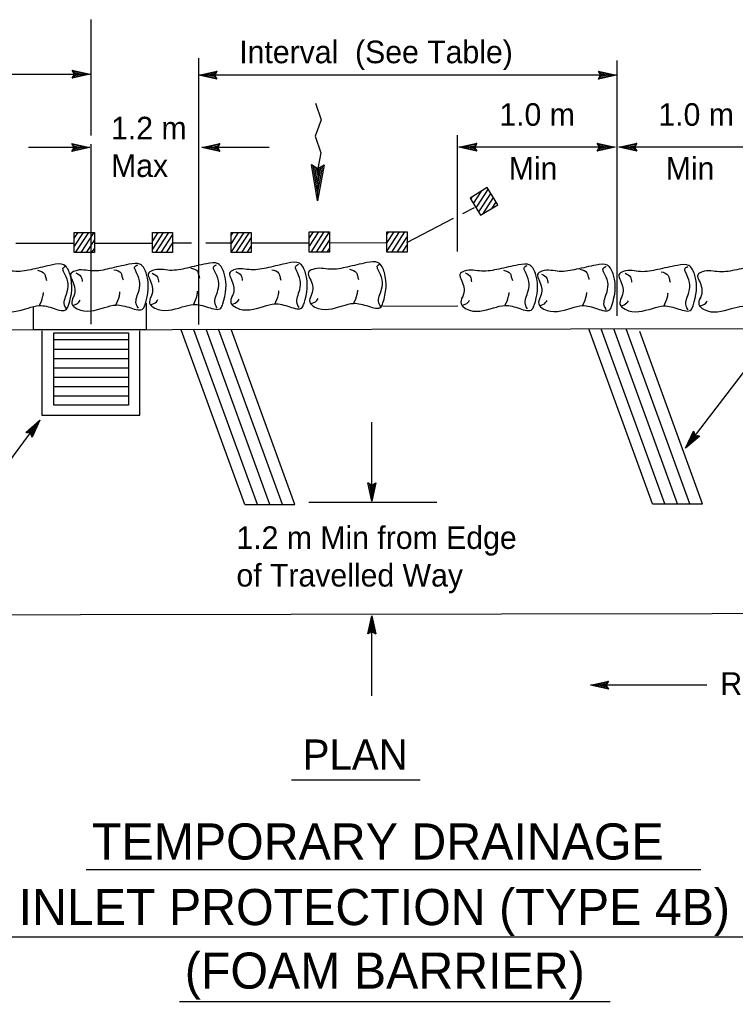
# Model space of a CAD drawing. Extents: x 6707406 to 6714471, y 1868570 to 1872341.
# Drawn here: x 6709693.1 to 6709921.3, y 1871409.2 to 1871722.3 of the extents above; entities that cross this region are included whole.
import ezdxf

# ---------------------------------------------------------------- set-up
doc = ezdxf.new("R2010")
doc.units = 0
for name, color, linetype in [('1 Control', 7, 'Continuous'), ('57 Undefined', 7, 'Continuous'), ('60 Nongeo Data', 7, 'Continuous'), ('63 Undefined', 7, 'Continuous')]:
    doc.layers.add(name, color=color, linetype=linetype)

msp = doc.modelspace()

# ---------------------------------------------------------------- linework, layer by layer
at = {"layer": '1 Control'}
for p, q in [((6709842.49, 1871668.29), (6709838.6, 1871662.29)), ((6709837.44, 1871665.8), (6709836.94, 1871665.03)), ((6709840.28, 1871667.52), (6709837.77, 1871663.66)), ((6709843.32, 1871666.92), (6709839.43, 1871660.93)), ((6709844.15, 1871665.55), (6709840.71, 1871660.25)), ((6709844.98, 1871664.19), (6709843.54, 1871661.97)), ((6709713.36, 1871654.41), (6709710.54, 1871650.07)), ((6709711.64, 1871654.41), (6709710.54, 1871652.71)), ((6709715.08, 1871654.41), (6709710.89, 1871647.97)), ((6709716.79, 1871654.41), (6709712.61, 1871647.97)), ((6709716.98, 1871652.05), (6709714.33, 1871647.97)), ((6709738.92, 1871654.41), (6709735.48, 1871649.11)), ((6709737.2, 1871654.41), (6709735.48, 1871651.75)), ((6709735.49, 1871654.41), (6709735.48, 1871654.39)), ((6709740.64, 1871654.41), (6709736.46, 1871647.97)), ((6709741.91, 1871653.73), (6709738.17, 1871647.97)), ((6709764.57, 1871654.41), (6709760.53, 1871648.19)), ((6709762.85, 1871654.41), (6709760.53, 1871650.84)), ((6709761.13, 1871654.41), (6709760.53, 1871653.48)), ((6709766.28, 1871654.41), (6709762.1, 1871647.97)), ((6709766.97, 1871652.82), (6709763.82, 1871647.97)), ((6709788.42, 1871654.6), (6709785.47, 1871650.05)), ((6709786.7, 1871654.6), (6709785.47, 1871652.7)), ((6709790.14, 1871654.6), (6709785.96, 1871648.16)), ((6709791.85, 1871654.6), (6709787.67, 1871648.16)), ((6709791.9, 1871652.03), (6709789.39, 1871648.16)), ((6709814.16, 1871654.6), (6709810.22, 1871648.53)), ((6709812.44, 1871654.6), (6709810.22, 1871651.17)), ((6709810.73, 1871654.6), (6709810.22, 1871653.82)), ((6709815.88, 1871654.6), (6709811.7, 1871648.16)), ((6709816.65, 1871653.15), (6709813.41, 1871648.16)), ((6709716.98, 1871649.4), (6709716.05, 1871647.97)), ((6709741.91, 1871651.08), (6709739.89, 1871647.97)), ((6709766.97, 1871650.17), (6709765.54, 1871647.97)), ((6709791.9, 1871649.39), (6709791.11, 1871648.16)), ((6709816.65, 1871650.51), (6709815.13, 1871648.16)), ((6709741.91, 1871648.44), (6709741.61, 1871647.97))]:
    msp.add_line(p, q, dxfattribs=at)
for points in [[(6709842.23, 1871668.71), (6709836.73, 1871665.37), (6709840.07, 1871659.87), (6709845.57, 1871663.2)], [(6709710.54, 1871654.41), (6709716.98, 1871654.41), (6709716.98, 1871647.97), (6709710.54, 1871647.97)], [(6709735.48, 1871654.41), (6709741.91, 1871654.41), (6709741.91, 1871647.97), (6709735.48, 1871647.97)], [(6709760.53, 1871654.41), (6709766.97, 1871654.41), (6709766.97, 1871647.97), (6709760.53, 1871647.97)], [(6709785.47, 1871654.6), (6709791.9, 1871654.6), (6709791.9, 1871648.16), (6709785.47, 1871648.16)], [(6709810.22, 1871654.6), (6709816.65, 1871654.6), (6709816.65, 1871648.16), (6709810.22, 1871648.16)]]:
    msp.add_lwpolyline(points, close=True, dxfattribs=at)
at = {"layer": '57 Undefined'}
for p, q in [((6709715.85, 1871722.28), (6709715.85, 1871685.32)), ((6709750.26, 1871625.05), (6709750.26, 1871709.96)), ((6709883.68, 1871627.81), (6709883.68, 1871709.2)), ((6709588.34, 1871704.86), (6709715.63, 1871704.86)), ((6709883.41, 1871704.6), (6709750.29, 1871704.6)), ((6709832.72, 1871648.29), (6709832.72, 1871685.42)), ((6709715.55, 1871681.47), (6709696, 1871681.47)), ((6709715.85, 1871682.57), (6709715.85, 1871625.12)), ((6709772.68, 1871681.47), (6709751.21, 1871681.47)), ((6709883.02, 1871681.58), (6709833.18, 1871681.58)), ((6709934.78, 1871681.58), (6709884.17, 1871681.58)), ((6709905.48, 1871585.64), (6709978.12, 1871680.81)), ((6709668.01, 1871551.82), (6709699.53, 1871594.51)), ((6709805.46, 1871568.74), (6709805.46, 1871593.84)), ((6709826.16, 1871568.32), (6709785.33, 1871568.32)), ((6709805.46, 1871506.6), (6709805.46, 1871532.11)), ((6709912.24, 1871510.02), (6709875.09, 1871510.02)), ((6709779.84, 1871479.86), (6709820.79, 1871479.86)), ((6709714.3, 1871451.17), (6709910.3, 1871451.17)), ((6709677.29, 1871429.73), (6709944.39, 1871429.73)), ((6709744.07, 1871409.15), (6709881.4, 1871409.15))]:
    msp.add_line(p, q, dxfattribs=at)
at = {"layer": '60 Nongeo Data'}
for p, q in [((6709709.87, 1871706.15), (6709709.87, 1871706.15)), ((6709756.05, 1871705.87), (6709756.05, 1871705.87)), ((6709877.65, 1871705.88), (6709877.65, 1871705.88)), ((6709709.87, 1871703.59), (6709709.87, 1871703.59)), ((6709715.63, 1871704.86), (6709715.63, 1871704.86)), ((6709750.29, 1871704.6), (6709750.29, 1871704.6)), ((6709756.05, 1871703.31), (6709756.05, 1871703.31)), ((6709877.65, 1871703.32), (6709877.65, 1871703.32)), ((6709883.41, 1871704.6), (6709883.41, 1871704.6)), ((6709709.8, 1871682.75), (6709709.8, 1871682.75)), ((6709715.55, 1871681.47), (6709715.55, 1871681.47)), ((6709751.21, 1871681.47), (6709751.21, 1871681.47)), ((6709756.97, 1871682.74), (6709756.97, 1871682.74)), ((6709833.18, 1871681.58), (6709833.18, 1871681.58)), ((6709838.94, 1871682.86), (6709838.94, 1871682.86)), ((6709838.94, 1871680.29), (6709838.94, 1871680.29)), ((6709877.26, 1871682.87), (6709877.26, 1871682.87)), ((6709877.26, 1871680.3), (6709877.26, 1871680.3)), ((6709883.02, 1871681.58), (6709883.02, 1871681.58)), ((6709884.17, 1871681.58), (6709884.17, 1871681.58)), ((6709889.93, 1871682.86), (6709889.93, 1871682.86)), ((6709889.93, 1871680.29), (6709889.93, 1871680.29)), ((6709709.8, 1871680.19), (6709709.8, 1871680.19)), ((6709756.97, 1871680.18), (6709756.97, 1871680.18)), ((6709764.96, 1871567.62), (6709744.67, 1871623.38)), ((6709768.94, 1871567.63), (6709748.65, 1871623.37)), ((6709772.92, 1871567.63), (6709752.57, 1871623.56)), ((6709776.9, 1871567.64), (6709756.55, 1871623.56)), ((6709780.89, 1871567.65), (6709760.64, 1871623.27)), ((6709894.89, 1871567.85), (6709874.57, 1871623.68)), ((6709898.88, 1871567.83), (6709878.55, 1871623.69)), ((6709902.87, 1871567.83), (6709882.54, 1871623.69)), ((6709906.85, 1871567.83), (6709886.52, 1871623.7)), ((6709910.82, 1871567.87), (6709890.82, 1871622.81)), ((6709704.01, 1871620.22), (6709727.8, 1871620.22)), ((6709704.01, 1871617.22), (6709727.8, 1871617.22)), ((6709704.01, 1871614.23), (6709727.8, 1871614.23)), ((6709704.01, 1871611.23), (6709727.8, 1871611.23)), ((6709704.01, 1871608.24), (6709727.8, 1871608.24)), ((6709704.01, 1871605.24), (6709727.8, 1871605.24)), ((6709704.01, 1871602.25), (6709727.8, 1871602.25)), ((6709699.53, 1871594.51), (6709699.53, 1871594.51)), ((6709695.07, 1871590.64), (6709695.07, 1871590.64)), ((6709907.96, 1871590.99), (6709907.96, 1871590.99)), ((6709909.99, 1871589.43), (6709909.99, 1871589.43)), ((6709697.13, 1871589.12), (6709697.13, 1871589.12)), ((6709905.48, 1871585.64), (6709905.48, 1871585.64)), ((6709804.19, 1871574.5), (6709804.19, 1871574.5)), ((6709806.75, 1871574.5), (6709806.75, 1871574.5)), ((6709805.46, 1871568.74), (6709805.46, 1871568.74)), ((6709805.46, 1871532.11), (6709805.46, 1871532.11)), ((6709804.18, 1871526.35), (6709804.18, 1871526.35)), ((6709806.74, 1871526.35), (6709806.74, 1871526.35)), ((6709880.85, 1871511.29), (6709880.85, 1871511.29)), ((6709875.09, 1871510.02), (6709875.09, 1871510.02)), ((6709880.85, 1871508.73), (6709880.85, 1871508.73))]:
    msp.add_line(p, q, dxfattribs=at)
for points in [[(6709709.87, 1871706.15), (6709715.63, 1871704.86), (6709709.87, 1871703.59), (6709710.08, 1871703.93), (6709714.3, 1871704.86), (6709710.08, 1871705.81), (6709710.28, 1871705.47), (6709712.98, 1871704.87), (6709710.28, 1871704.27), (6709710.49, 1871704.61), (6709711.65, 1871704.87), (6709710.48, 1871705.13), (6709710.64, 1871704.86), (6709709.87, 1871703.59), (6709710.64, 1871704.86)], [(6709756.05, 1871703.31), (6709750.29, 1871704.6), (6709756.05, 1871705.87), (6709755.85, 1871705.53), (6709751.63, 1871704.6), (6709755.85, 1871703.65), (6709755.64, 1871703.99), (6709752.94, 1871704.59), (6709755.64, 1871705.19), (6709755.44, 1871704.85), (6709754.27, 1871704.59), (6709755.44, 1871704.33), (6709755.28, 1871704.6), (6709756.05, 1871705.87), (6709755.28, 1871704.6)], [(6709877.65, 1871705.88), (6709883.41, 1871704.6), (6709877.65, 1871703.32), (6709877.85, 1871703.66), (6709882.07, 1871704.59), (6709877.85, 1871705.54), (6709878.05, 1871705.2), (6709880.75, 1871704.6), (6709878.05, 1871704), (6709878.26, 1871704.34), (6709879.43, 1871704.6), (6709878.26, 1871704.86), (6709878.41, 1871704.6), (6709877.65, 1871703.32), (6709878.41, 1871704.6)], [(6709709.8, 1871682.75), (6709715.55, 1871681.47), (6709709.79, 1871680.19), (6709710, 1871680.53), (6709714.22, 1871681.46), (6709710, 1871682.41), (6709710.2, 1871682.07), (6709712.9, 1871681.47), (6709710.2, 1871680.87), (6709710.41, 1871681.21), (6709711.58, 1871681.47), (6709710.41, 1871681.73), (6709710.56, 1871681.47), (6709709.79, 1871680.19), (6709710.56, 1871681.47)], [(6709756.97, 1871680.18), (6709751.21, 1871681.47), (6709756.97, 1871682.74), (6709756.77, 1871682.4), (6709752.55, 1871681.47), (6709756.77, 1871680.52), (6709756.56, 1871680.86), (6709753.86, 1871681.47), (6709756.56, 1871682.06), (6709756.36, 1871681.72), (6709755.19, 1871681.46), (6709756.36, 1871681.2), (6709756.2, 1871681.47), (6709756.97, 1871682.74), (6709756.2, 1871681.47)], [(6709838.94, 1871680.29), (6709833.18, 1871681.58), (6709838.94, 1871682.86), (6709838.74, 1871682.52), (6709834.52, 1871681.58), (6709838.74, 1871680.64), (6709838.53, 1871680.98), (6709835.83, 1871681.58), (6709838.53, 1871682.18), (6709838.33, 1871681.84), (6709837.16, 1871681.58), (6709838.33, 1871681.32), (6709838.17, 1871681.58), (6709838.94, 1871682.86), (6709838.17, 1871681.58)], [(6709877.26, 1871682.87), (6709883.02, 1871681.58), (6709877.26, 1871680.3), (6709877.47, 1871680.64), (6709881.69, 1871681.58), (6709877.47, 1871682.53), (6709877.67, 1871682.19), (6709880.37, 1871681.58), (6709877.67, 1871680.99), (6709877.88, 1871681.33), (6709879.04, 1871681.58), (6709877.87, 1871681.85), (6709878.03, 1871681.58), (6709877.26, 1871680.3), (6709878.03, 1871681.58)], [(6709889.93, 1871680.29), (6709884.17, 1871681.58), (6709889.93, 1871682.86), (6709889.73, 1871682.52), (6709885.51, 1871681.58), (6709889.73, 1871680.64), (6709889.53, 1871680.98), (6709886.82, 1871681.58), (6709889.52, 1871682.18), (6709889.32, 1871681.84), (6709888.15, 1871681.58), (6709889.32, 1871681.32), (6709889.16, 1871681.58), (6709889.93, 1871682.86), (6709889.16, 1871681.58)], [(6709704.01, 1871622.39), (6709727.8, 1871622.39), (6709727.8, 1871599.26), (6709704.01, 1871599.26)], [(6709695.07, 1871590.64), (6709699.53, 1871594.51), (6709697.13, 1871589.12), (6709696.98, 1871589.49), (6709698.74, 1871593.44), (6709695.47, 1871590.6), (6709695.86, 1871590.57), (6709697.95, 1871592.38), (6709696.83, 1871589.85), (6709696.68, 1871590.22), (6709697.16, 1871591.31), (6709696.26, 1871590.53), (6709696.56, 1871590.5), (6709697.13, 1871589.12), (6709696.56, 1871590.5)], [(6709909.99, 1871589.43), (6709905.48, 1871585.64), (6709907.96, 1871590.99), (6709908.1, 1871590.62), (6709906.28, 1871586.7), (6709909.6, 1871589.48), (6709909.2, 1871589.52), (6709907.09, 1871587.74), (6709908.25, 1871590.25), (6709908.39, 1871589.88), (6709907.89, 1871588.8), (6709908.81, 1871589.57), (6709908.5, 1871589.6), (6709907.96, 1871590.99), (6709908.5, 1871589.6)], [(6709806.75, 1871574.5), (6709805.46, 1871568.74), (6709804.19, 1871574.5), (6709804.53, 1871574.29), (6709805.46, 1871570.07), (6709806.41, 1871574.29), (6709806.07, 1871574.09), (6709805.47, 1871571.39), (6709804.87, 1871574.09), (6709805.21, 1871573.88), (6709805.47, 1871572.72), (6709805.73, 1871573.89), (6709805.46, 1871573.73), (6709804.19, 1871574.5), (6709805.46, 1871573.73)], [(6709804.18, 1871526.35), (6709805.46, 1871532.11), (6709806.74, 1871526.35), (6709806.4, 1871526.55), (6709805.47, 1871530.77), (6709804.52, 1871526.55), (6709804.86, 1871526.75), (6709805.46, 1871529.46), (6709806.06, 1871526.76), (6709805.72, 1871526.96), (6709805.46, 1871528.13), (6709805.2, 1871526.96), (6709805.46, 1871527.12), (6709806.74, 1871526.35), (6709805.46, 1871527.12)], [(6709880.85, 1871508.73), (6709875.09, 1871510.02), (6709880.85, 1871511.29), (6709880.65, 1871510.95), (6709876.43, 1871510.02), (6709880.65, 1871509.07), (6709880.44, 1871509.41), (6709877.74, 1871510.01), (6709880.44, 1871510.61), (6709880.24, 1871510.27), (6709879.07, 1871510.01), (6709880.24, 1871509.75), (6709880.08, 1871510.02), (6709880.85, 1871511.29), (6709880.08, 1871510.02)]]:
    msp.add_lwpolyline(points, close=True, dxfattribs=at)
for points in [[(6709834.39, 1871660.45), (6709838.15, 1871662.4)], [(6709816.54, 1871651.16), (6709831.45, 1871658.92)], [(6709691.87, 1871650.96), (6709710.37, 1871650.99)], [(6709716.99, 1871651), (6709735.4, 1871651.03)], [(6709742.03, 1871651.04), (6709747.94, 1871651.05)], [(6709752.53, 1871651.06), (6709760.39, 1871651.07)], [(6709767.14, 1871651.08), (6709785.43, 1871651.11)], [(6709791.92, 1871651.12), (6709809.92, 1871651.15)], [(6709697.4, 1871630.53), (6709697.4, 1871623.44), (6709733.57, 1871623.44), (6709733.57, 1871631.87)], [(6709808.89, 1871630.92), (6709832.88, 1871630.96)], [(6709678.2, 1871623.36), (6709932.4, 1871623.77)], [(6709700.23, 1871622.97), (6709700.23, 1871596.11), (6709731.47, 1871596.11), (6709731.47, 1871622.97)], [(6709764.96, 1871567.62), (6709780.89, 1871567.65)], [(6709894.89, 1871567.85), (6709910.82, 1871567.87)], [(6709578.14, 1871532.3), (6710048.25, 1871533.08)]]:
    msp.add_lwpolyline(points, dxfattribs=at)
for points in [[(6709685.81, 1871633.55), (6709685.41, 1871631.49), (6709687.07, 1871629.88), (6709695.81, 1871630.27), (6709699.39, 1871631.08), (6709704.17, 1871630.12), (6709708.12, 1871629.94), (6709708.74, 1871631.23), (6709709.2, 1871640.9), (6709707.25, 1871644.03), (6709703.6, 1871644.06), (6709697.36, 1871642.67), (6709691.88, 1871641.95), (6709686.33, 1871641.92), (6709684.96, 1871640.86), (6709685.47, 1871639.03), (6709686.2, 1871634.53), (6709685.73, 1871633.32)], [(6709708.12, 1871629.86), (6709707.45, 1871631.24), (6709708.32, 1871635.57), (6709708.49, 1871638.62), (6709707.15, 1871641.98), (6709706.93, 1871642.89), (6709707.93, 1871643.72)], [(6709710.2, 1871633.73), (6709709.8, 1871631.68), (6709711.46, 1871630.07), (6709720.2, 1871630.45), (6709723.78, 1871631.26), (6709728.56, 1871630.31), (6709732.51, 1871630.12), (6709733.13, 1871631.41), (6709733.59, 1871641.08), (6709731.64, 1871644.22), (6709727.99, 1871644.25), (6709721.75, 1871642.85), (6709716.27, 1871642.13), (6709710.72, 1871642.1), (6709709.35, 1871641.05), (6709709.86, 1871639.21), (6709710.59, 1871634.72), (6709710.12, 1871633.5)], [(6709730.99, 1871630.25), (6709730.31, 1871631.63), (6709731.19, 1871635.96), (6709731.36, 1871639), (6709730.02, 1871642.36), (6709729.8, 1871643.28), (6709730.79, 1871644.11)], [(6709734.97, 1871633.91), (6709734.57, 1871631.86), (6709736.23, 1871630.25), (6709744.97, 1871630.63), (6709748.55, 1871631.44), (6709753.33, 1871630.49), (6709757.28, 1871630.3), (6709757.9, 1871631.59), (6709758.36, 1871641.26), (6709756.41, 1871644.4), (6709752.76, 1871644.43), (6709746.52, 1871643.03), (6709741.04, 1871642.31), (6709735.49, 1871642.28), (6709734.12, 1871641.23), (6709734.63, 1871639.4), (6709735.36, 1871634.9), (6709734.89, 1871633.68)], [(6709747.59, 1871643.1), (6709749.86, 1871641.94), (6709750.15, 1871641.02), (6709750.52, 1871639.8)], [(6709756.14, 1871630.24), (6709755.46, 1871631.61), (6709756.34, 1871635.95), (6709756.51, 1871638.99), (6709755.17, 1871642.35), (6709754.95, 1871643.27), (6709755.94, 1871644.1)], [(6709760.88, 1871634.08), (6709760.49, 1871632.03), (6709762.15, 1871630.42), (6709770.89, 1871630.8), (6709774.47, 1871631.61), (6709779.25, 1871630.66), (6709783.2, 1871630.48), (6709783.81, 1871631.77), (6709784.27, 1871641.43), (6709782.32, 1871644.57), (6709778.67, 1871644.6), (6709772.43, 1871643.2), (6709766.95, 1871642.48), (6709761.41, 1871642.45), (6709760.03, 1871641.4), (6709760.55, 1871639.57), (6709761.27, 1871635.07), (6709760.81, 1871633.85)], [(6709782.24, 1871630.41), (6709781.57, 1871631.78), (6709782.44, 1871636.12), (6709782.62, 1871639.16), (6709781.28, 1871642.52), (6709781.06, 1871643.44), (6709782.05, 1871644.27)], [(6709786.04, 1871634.26), (6709785.64, 1871632.21), (6709787.3, 1871630.6), (6709796.04, 1871630.98), (6709799.62, 1871631.79), (6709804.4, 1871630.84), (6709808.35, 1871630.65), (6709808.96, 1871631.94), (6709809.42, 1871641.61), (6709807.47, 1871644.75), (6709803.83, 1871644.77), (6709797.58, 1871643.38), (6709792.11, 1871642.66), (6709786.56, 1871642.63), (6709785.18, 1871641.58), (6709785.7, 1871639.74), (6709786.42, 1871635.25), (6709785.96, 1871634.03)], [(6709798.26, 1871642.69), (6709800.53, 1871641.53), (6709800.83, 1871640.61), (6709801.2, 1871639.39)], [(6709808.35, 1871630.58), (6709807.67, 1871631.95), (6709808.54, 1871636.29), (6709808.72, 1871639.33), (6709807.38, 1871642.69), (6709807.16, 1871643.61), (6709808.15, 1871644.44)], [(6709834.27, 1871633.71), (6709833.86, 1871631.67), (6709835.5, 1871630.04), (6709844.24, 1871630.34), (6709847.83, 1871631.11), (6709852.6, 1871630.11), (6709856.55, 1871629.89), (6709857.18, 1871631.17), (6709857.73, 1871640.83), (6709855.81, 1871643.99), (6709852.17, 1871644.05), (6709845.91, 1871642.72), (6709840.43, 1871642.06), (6709834.88, 1871642.08), (6709833.49, 1871641.04), (6709833.99, 1871639.2), (6709834.67, 1871634.7), (6709834.19, 1871633.49)], [(6709855.03, 1871630.03), (6709854.37, 1871631.41), (6709855.28, 1871635.74), (6709855.49, 1871638.78), (6709854.18, 1871642.15), (6709853.97, 1871643.07), (6709854.97, 1871643.89)], [(6709859.04, 1871633.65), (6709858.63, 1871631.6), (6709860.27, 1871629.97), (6709869.02, 1871630.27), (6709872.6, 1871631.05), (6709877.37, 1871630.05), (6709881.32, 1871629.82), (6709881.95, 1871631.11), (6709882.5, 1871640.77), (6709880.58, 1871643.93), (6709876.94, 1871643.99), (6709870.68, 1871642.66), (6709865.2, 1871641.99), (6709859.65, 1871642.02), (6709858.26, 1871640.98), (6709858.76, 1871639.14), (6709859.44, 1871634.63), (6709858.96, 1871633.42)], [(6709871.75, 1871642.71), (6709874.01, 1871641.53), (6709874.3, 1871640.61), (6709874.65, 1871639.39)], [(6709880.18, 1871629.77), (6709879.52, 1871631.15), (6709880.43, 1871635.48), (6709880.64, 1871638.52), (6709879.33, 1871641.89), (6709879.12, 1871642.81), (6709880.12, 1871643.63)], [(6709884.96, 1871633.57), (6709884.54, 1871631.52), (6709886.19, 1871629.89), (6709894.93, 1871630.19), (6709898.52, 1871630.96), (6709903.29, 1871629.96), (6709907.23, 1871629.74), (6709907.86, 1871631.02), (6709908.42, 1871640.69), (6709906.5, 1871643.84), (6709902.85, 1871643.91), (6709896.6, 1871642.57), (6709891.11, 1871641.91), (6709885.57, 1871641.93), (6709884.18, 1871640.89), (6709884.68, 1871639.05), (6709885.36, 1871634.55), (6709884.88, 1871633.34)], [(6709906.28, 1871629.68), (6709905.62, 1871631.06), (6709906.53, 1871635.39), (6709906.74, 1871638.43), (6709905.43, 1871641.8), (6709905.22, 1871642.72), (6709906.22, 1871643.54)], [(6709910.11, 1871633.5), (6709909.69, 1871631.45), (6709911.34, 1871629.82), (6709920.08, 1871630.12), (6709923.67, 1871630.89), (6709928.44, 1871629.89), (6709932.39, 1871629.67), (6709933.02, 1871630.95), (6709933.57, 1871640.61), (6709931.65, 1871643.77), (6709928, 1871643.84), (6709921.75, 1871642.5), (6709916.26, 1871641.84), (6709910.72, 1871641.86), (6709909.33, 1871640.82), (6709909.83, 1871638.98), (6709910.51, 1871634.48), (6709910.03, 1871633.27)], [(6709698.8, 1871642.35), (6709701.07, 1871641.19), (6709701.37, 1871640.27), (6709701.74, 1871639.05)], [(6709711.03, 1871641.56), (6709712.69, 1871640.33), (6709713.06, 1871638.73)], [(6709723.19, 1871642.53), (6709725.46, 1871641.37), (6709725.76, 1871640.46), (6709726.13, 1871639.24)], [(6709735.41, 1871641.37), (6709737.08, 1871640.14), (6709737.44, 1871638.54)], [(6709762.09, 1871641.91), (6709763.75, 1871640.68), (6709764.12, 1871639.08)], [(6709773.49, 1871642.51), (6709775.76, 1871641.35), (6709776.06, 1871640.43), (6709776.43, 1871639.21)], [(6709835.18, 1871641.54), (6709836.83, 1871640.29), (6709837.18, 1871638.69)], [(6709847.35, 1871642.39), (6709849.61, 1871641.21), (6709849.9, 1871640.29), (6709850.26, 1871639.06)], [(6709859.56, 1871641.1), (6709861.21, 1871639.86), (6709861.56, 1871638.25)], [(6709886.24, 1871641.39), (6709887.89, 1871640.14), (6709888.25, 1871638.53)], [(6709897.65, 1871641.87), (6709899.91, 1871640.69), (6709900.2, 1871639.77), (6709900.55, 1871638.54)], [(6709699.39, 1871631), (6709700.56, 1871634.04), (6709700.72, 1871635.25)], [(6709723.78, 1871631.18), (6709724.94, 1871634.22), (6709725.11, 1871635.44)], [(6709748.55, 1871631.36), (6709749.72, 1871634.4), (6709749.88, 1871635.62)], [(6709774.46, 1871631.54), (6709775.63, 1871634.57), (6709775.79, 1871635.79)], [(6709785.86, 1871631.67), (6709787.85, 1871632.65), (6709788.31, 1871633.33)], [(6709799.62, 1871631.71), (6709800.78, 1871634.75), (6709800.94, 1871635.97)], [(6709847.83, 1871631.03), (6709849.02, 1871634.06), (6709849.2, 1871635.27)], [(6709872.6, 1871630.97), (6709873.79, 1871634), (6709873.97, 1871635.21)], [(6709898.51, 1871630.89), (6709899.71, 1871633.91), (6709899.88, 1871635.13)], [(6709710.03, 1871631.14), (6709712.01, 1871632.12), (6709712.47, 1871632.8)], [(6709734.8, 1871631.32), (6709736.78, 1871632.3), (6709737.24, 1871632.98)], [(6709760.71, 1871631.49), (6709762.69, 1871632.47), (6709763.16, 1871633.15)], [(6709834.08, 1871631.13), (6709836.07, 1871632.08), (6709836.54, 1871632.76)], [(6709858.85, 1871631.07), (6709860.84, 1871632.02), (6709861.31, 1871632.7)], [(6709884.76, 1871630.98), (6709886.75, 1871631.94), (6709887.22, 1871632.61)], [(6709909.91, 1871630.91), (6709911.91, 1871631.86), (6709912.37, 1871632.54)]]:
    msp.add_spline(points, degree=3, dxfattribs=at)
at = {"layer": '63 Undefined'}
for p, q in [((6709788.09, 1871664.49), (6709786.15, 1871676.05)), ((6709786.15, 1871676.05), (6709788.18, 1871674.85)), ((6709788.11, 1871667.25), (6709786.69, 1871675.73)), ((6709788.14, 1871669.99), (6709787.23, 1871675.4)), ((6709788.16, 1871672.79), (6709787.78, 1871675.08)), ((6709790.23, 1871676.01), (6709788.09, 1871664.49)), ((6709789.69, 1871675.7), (6709788.11, 1871667.25)), ((6709789.14, 1871675.39), (6709788.14, 1871669.99)), ((6709788.59, 1871675.07), (6709788.16, 1871672.79)), ((6709788.18, 1871674.85), (6709790.23, 1871676.01))]:
    msp.add_line(p, q, dxfattribs=at)
msp.add_lwpolyline([(6709787.42, 1871695.63), (6709789.27, 1871690.32), (6709787.32, 1871685.06), (6709789.18, 1871679.76), (6709788.18, 1871674.85), (6709788.09, 1871664.49)], dxfattribs=at)

# ---------------------------------------------------------------- texts
at = {"layer": '57 Undefined'}
for s, height, p in [('Interval  (See Table)', 7.1998, (6709763.15, 1871708.37)), ('1.0 m', 7.2, (6709846.08, 1871688.42)), ('1.0 m', 7.2, (6709896.79, 1871688.42)), ('1.2 m', 7.2, (6709722.28, 1871684.09)), ('Max', 7.2, (6709722.28, 1871672.09)), ('Min', 7.2, (6709849.07, 1871671.25)), ('Min', 7.2, (6709899.12, 1871671.25)), ('1.2 m Min from Edge ', 7.1998, (6709762.25, 1871553.46)), ('of Travelled Way', 7.1998, (6709762.25, 1871541.46)), ('ROADWAY', 7.2, (6709916.54, 1871506.91)), ('PLAN', 9.6, (6709783.35, 1871483.08)), ('TEMPORARY DRAINAGE', 11.5197, (6709716.18, 1871454.39)), ('INLET PROTECTION (TYPE 4B)', 11.5197, (6709692.79, 1871433.47)), ('(FOAM BARRIER)', 11.5197, (6709745.79, 1871413.21))]:
    msp.add_text(s, height=height, dxfattribs=at).set_placement(p)

doc.saveas('drawing.dxf')
